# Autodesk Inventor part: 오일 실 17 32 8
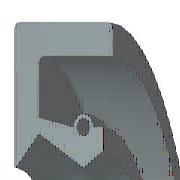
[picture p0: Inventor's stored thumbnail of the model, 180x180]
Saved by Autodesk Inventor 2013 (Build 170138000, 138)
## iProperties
IsCustomPart: 0
Created: 2018-09
Part Number: 오일 실 17 32 8
Material: 고무
Description: 오일-실
Document SubType Name: Modeling
Standard: KS B 2804
Standards Organization: KS
Language: ko-KR
Size Designation: D - 17 32 8
Categories: <MemberInstance><Categories><Category DisplayName="샤프트 부품" InternalName="7f7aeb1f-a693-4053-b835-cee3144e0d98" Mnemonic="SHFT"><Category DisplayName="실링" Intern
Density: 0.93 g/cm^3
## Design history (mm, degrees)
revolve "본체" stored, may be unused: angle "d17" = 90 deg
revolve "스프링1" stored, may be unused: angle "d18" = 90 deg
body "Solid1"
sketch "스케치1"
  geometry: L1 (0, 16)-(8, 16); L2 (8, 14.25)-(1.75, 14.25); L3 (1.75, 10.25)-(4.9, 8.5); L4 (4.9, 8.5)-(0, 8.5); L5 (0, 0)-(9.586, 0) reference; L6 (4.9, 8.5)-(6.3, 9.375); L7 (0, 18)-(0, -3) reference; L8 (-1.941, 0)-(11.507, 0) reference; L9 (4.2, 10.6)-(1.75, 11.21); L10 (1.75, 11.21)-(1.75, 14.25); L11 (0, 16)-(0, 8.588); L12 (4.9, 8.5)-(0, 8.5); L13 (1.75, 10.25)-(0.152, 8.528); L14 (8, 16)-(8, 14.25); L15 (5.6, 10.6)-(6.3, 10.6); L16 (6.3, 10.6)-(6.3, 9.375); C1 r 0.455 at (4.9, 10.6); A1 r 0.7 centre (4.9, 10.6) between (5.6, 10.6) and (4.2, 10.6); A2 r 0.088 centre (0.088, 8.588) between (0, 8.588) and (0.152, 8.528); 1 further point
  constraints: 28 end point, 5 horizontal alignment, 5 point on line, 4 point on circle, 4 vertical alignment, 3 centre point, 3 tangent, 2 collinear, 2 horizontal, 2 perpendicular, 1 coincident, 1 parallel
  dimensions: "d0" = 32 diameter of L1 L5 (= SD2); "d1" = 1.75 distance of L1.end L2.start (= SD); "d2" = 0.91 diameter of C1 (= SPDI); "d3" = 1.4 diameter of A1 (= SPDA); "d4" = 17 diameter of L3.end L5 (= NND); "d5" = 20.5 diameter of L3.start L5 (= TKDM); "d7" = 22.42 diameter of L9.end L5 (= TKDM + 0.24 x SWDT); "d8" = 1.75 distance between parallel lines of L11 L10 (= SD); "d9" = 4.9 distance from line of L11 C1.centre (= SPDST); "d10" = 21.2 diameter of C1.centre L5 (= HLDM); "d11" = 0.0875 radius of A2 (= 0.25 x LAB); "d12" = 6.3 distance between parallel lines of L11 L16 (= SDI); "d13" = 18.75 diameter of L6.end L5 (= ABDM); "d14" = 8 distance from line of L11 L1.end (= SWDT)
fillet "모깎기1" dims "d6" = 0.3 (= RR)
other parameters: "SD2" = 32 [user parameter; used in 1 equation term], "SWDT" = 8 [user parameter; used in 2 equation terms], "RR" = 0.3 [user parameter; used in 1 equation term], "SD" = 1.75 [user parameter; used in 2 equation terms], "NND" = 17 [user parameter; used in 1 equation term], "SPDA" = 1.4 [user parameter; used in 1 equation term], "SPDI" = 0.91 [user parameter; used in 1 equation term], "TKDM" = 20.5 [user parameter; used in 2 equation terms], "HLDM" = 21.2 [user parameter; used in 1 equation term], "ABDM" = 18.75 [user parameter; used in 1 equation term], "SDI" = 6.3 [user parameter; used in 1 equation term], "SPDST" = 4.9 [user parameter; used in 1 equation term], "LAB" = 0.35 [user parameter; used in 1 equation term], "d15" = 0, "d16" = 0, "d19" = 0
